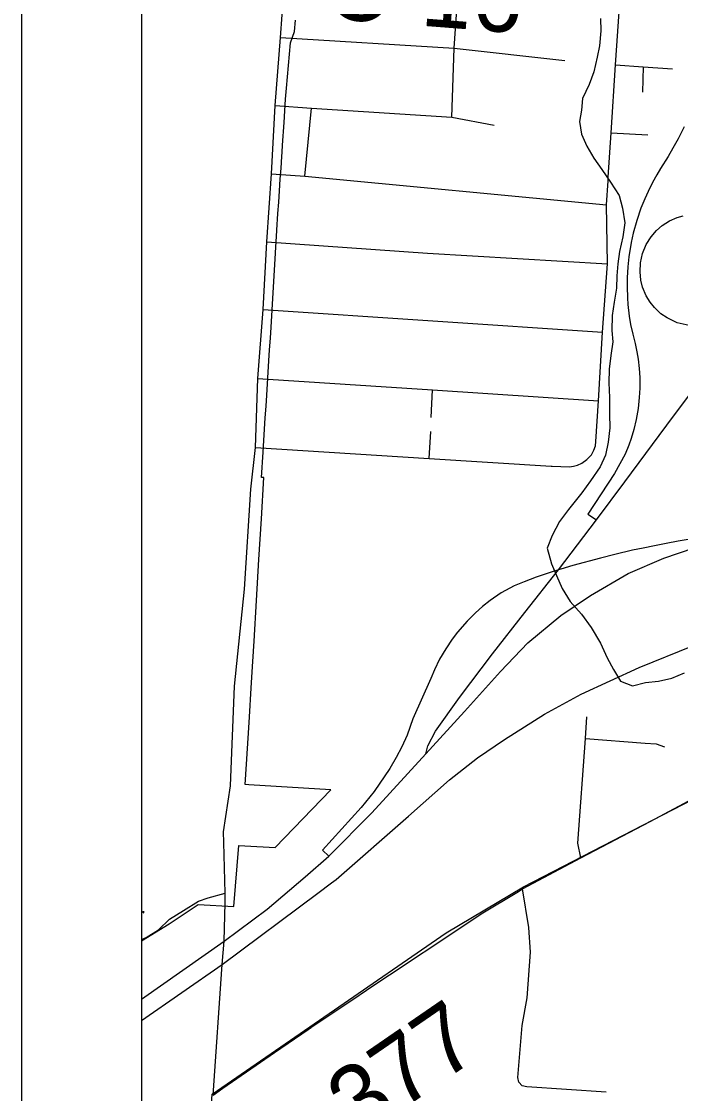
# Model space of a CAD drawing. Extents: x 208586767.6 to 208586821.4, y -134301046.9 to -134301022.9.
# Drawn here: x 208586777.928 to 208586778.476, y -134301030.451 to -134301029.559 of the extents above; entities that cross this region are included whole.
import ezdxf

# ---------------------------------------------------------------- set-up
doc = ezdxf.new("R2010")
doc.units = 0
for name, color, linetype in [('GM_X_City_Street', 7, 'Continuous'), ('GM_X_Corporation', 7, 'Continuous'), ('GM_X_County_Road', 7, 'Continuous'), ('GM_X_County_Road_Text', 7, 'Continuous'), ('GM_X_Interchange_Ramps', 7, 'Continuous'), ('GM_X_Interstate_Route', 7, 'Continuous'), ('GM_X_Minor_River', 7, 'Continuous'), ('GM_X_Rail_Line', 7, 'Continuous'), ('GM_X_Township_Road', 7, 'Continuous'), ('GM_X_US_Route', 7, 'Continuous'), ('SH_Data', 7, 'Continuous')]:
    doc.layers.add(name, color=color, linetype=linetype)

msp = doc.modelspace()

# ---------------------------------------------------------------- linework, layer by layer
at = {"layer": 'GM_X_City_Street'}
msp.add_lwpolyline([(208586778.41474, -134301030.44948), (208586778.34869, -134301030.44514), (208586778.34476, -134301030.44426), (208586778.34194, -134301030.4414), (208586778.34112, -134301030.43746), (208586778.34483, -134301030.39406), (208586778.34883, -134301030.37122), (208586778.35154, -134301030.33312), (208586778.35037, -134301030.31257), (208586778.34509, -134301030.28063)], dxfattribs=at)
at = {"layer": 'GM_X_Corporation'}
for points in [[(208586778.02826, -134301025.18459), (208586778.02826, -134301030.32371), (208586778.05119, -134301030.30976), (208586778.07514, -134301030.29348), (208586778.10481, -134301030.29512), (208586778.10901, -134301030.2444), (208586778.11421, -134301030.24486), (208586778.13931, -134301030.2462), (208586778.18558, -134301030.19823), (208586778.1173, -134301030.19406), (208586778.11446, -134301030.19389), (208586778.11549, -134301030.17691), (208586778.1176, -134301030.14213), (208586778.11963, -134301030.10887), (208586778.12067, -134301030.0916), (208586778.1217, -134301030.07469), (208586778.12376, -134301030.0408), (208586778.12583, -134301030.0068), (208586778.12789, -134301029.97281), (208586778.12997, -134301029.93865), (208586778.12789, -134301029.93851), (208586778.1293, -134301029.91742), (208586778.12984, -134301029.90774), (208586778.13044, -134301029.8985), (208586778.13106, -134301029.88898), (208586778.13169, -134301029.87934), (208586778.13229, -134301029.87005), (208586778.1329, -134301029.86056), (208586778.13355, -134301029.85095), (208586778.13413, -134301029.84166), (208586778.13469, -134301029.83249), (208586778.13529, -134301029.82283), (208586778.13586, -134301029.81355), (208586778.13645, -134301029.80405), (208586778.13703, -134301029.79437), (208586778.13758, -134301029.78506), (208586778.13813, -134301029.77572), (208586778.1387, -134301029.76613), (208586778.13926, -134301029.75668), (208586778.13983, -134301029.74717), (208586778.14038, -134301029.73798), (208586778.14102, -134301029.72835), (208586778.14132, -134301029.72374), (208586778.14163, -134301029.71904), (208586778.14225, -134301029.70961), (208586778.14288, -134301029.7001), (208586778.1435, -134301029.69061), (208586778.14424, -134301029.68128), (208586778.14486, -134301029.67177), (208586778.1451, -134301029.66803), (208586778.14546, -134301029.66236), (208586778.14668, -134301029.64333), (208586778.1473, -134301029.63369), (208586778.14802, -134301029.62415), (208586778.14882, -134301029.61501), (208586778.14965, -134301029.60558), (208586778.15049, -134301029.5961), (208586778.15132, -134301029.58672), (208586778.15216, -134301029.57717), (208586778.1554, -134301029.56777), (208586778.15619, -134301029.55835)], [(208586778.02826, -134301026.87222), (208586778.02826, -134301030.84072), (208586780.45606, -134301030.84072), (208586780.46226, -134301030.73232), (208586780.4715, -134301030.56429), (208586780.4725, -134301030.5433), (208586780.47482, -134301030.49456), (208586780.47836, -134301030.43953), (208586780.48165, -134301030.41091), (208586780.49647, -134301030.208), (208586780.51007, -134301029.93716), (208586780.52674, -134301029.60513), (208586780.54433, -134301029.31871), (208586780.54744, -134301029.28003), (208586780.55021, -134301029.2296), (208586780.55566, -134301029.13188), (208586780.5628, -134301029.05207), (208586780.56784, -134301028.98117), (208586780.57226, -134301028.915), (208586780.57856, -134301028.81386), (208586780.60576, -134301028.40742)]]:
    msp.add_lwpolyline(points, dxfattribs=at)
at = {"layer": 'GM_X_County_Road'}
msp.add_line((208586778.08778, -134301030.45204), (208586778.09587, -134301030.4464), dxfattribs=at)
for points in [[(208586778.09662, -134301030.24215), (208586778.09638, -134301030.23312), (208586778.1022, -134301030.19496), (208586778.10543, -134301030.11216), (208586778.11384, -134301030.03128), (208586778.11894, -134301029.94838), (208586778.1229, -134301029.91373), (208586778.12488, -134301029.85633), (208586778.12933, -134301029.79892), (208586778.1323, -134301029.7425), (208586778.13626, -134301029.68608), (208586778.13923, -134301029.62917), (208586778.14368, -134301029.57275), (208586778.14783, -134301029.51583), (208586778.15165, -134301029.45691), (208586778.15187, -134301029.4532), (208586778.15344, -134301029.42722)], [(208586778.34173, -134301030.28266), (208586778.34509, -134301030.28063), (208586778.39368, -134301030.25482), (208586778.45133, -134301030.22449), (208586778.5031, -134301030.19684), (208586778.54251, -134301030.17641)], [(208586778.09758, -134301030.29227), (208586778.09776, -134301030.28429), (208586778.09662, -134301030.24215)], [(208586778.23453, -134301030.352), (208586778.29136, -134301030.31426), (208586778.31066, -134301030.30141), (208586778.34173, -134301030.28266)], [(208586778.08778, -134301030.45204), (208586778.09522, -134301030.34335), (208586778.09683, -134301030.32418), (208586778.09758, -134301030.29227)], [(208586778.20999, -134301030.3684), (208586778.22053, -134301030.3613), (208586778.23453, -134301030.352)], [(208586778.18561, -134301030.38483), (208586778.18643, -134301030.38427), (208586778.20918, -134301030.36894), (208586778.20999, -134301030.3684)], [(208586778.16911, -134301030.39594), (208586778.1699, -134301030.39541), (208586778.17817, -134301030.38984), (208586778.18561, -134301030.38483)], [(208586778.09587, -134301030.4464), (208586778.13874, -134301030.41652), (208586778.16675, -134301030.39753), (208586778.16911, -134301030.39594)]]:
    msp.add_lwpolyline(points, dxfattribs=at)
at = {"layer": 'GM_X_Interchange_Ramps'}
for points in [[(208586778.47941, -134301029.64708), (208586778.47442, -134301029.65697), (208586778.47014, -134301029.66481), (208586778.46614, -134301029.67169), (208586778.45983, -134301029.68164), (208586778.45672, -134301029.68682), (208586778.45307, -134301029.69344), (208586778.44943, -134301029.70075), (208586778.44664, -134301029.70702), (208586778.44357, -134301029.71471), (208586778.44008, -134301029.72501), (208586778.4372, -134301029.73554), (208586778.43553, -134301029.74309), (208586778.43354, -134301029.75522), (208586778.43268, -134301029.76332), (208586778.43213, -134301029.77269), (208586778.43202, -134301029.78012), (208586778.43231, -134301029.78923), (208586778.43271, -134301029.79474), (208586778.43379, -134301029.80435), (208586778.43494, -134301029.81146), (208586778.43671, -134301029.8195), (208586778.43874, -134301029.82717), (208586778.44019, -134301029.83408), (208586778.44118, -134301029.84009), (208586778.44208, -134301029.84784), (208586778.44254, -134301029.85531), (208586778.44259, -134301029.86435), (208586778.44219, -134301029.87212), (208586778.44119, -134301029.88124), (208586778.43961, -134301029.89029), (208586778.43761, -134301029.89871), (208586778.43538, -134301029.90615), (208586778.4335, -134301029.91155), (208586778.43038, -134301029.91928), (208586778.42158, -134301029.93532), (208586778.3995, -134301029.96915), (208586778.40669, -134301029.97371)], [(208586778.48359, -134301029.81225), (208586778.47364, -134301029.80992), (208586778.46524, -134301029.80595), (208586778.4602, -134301029.80243), (208586778.4548, -134301029.79736), (208586778.45115, -134301029.79281), (208586778.44794, -134301029.78748), (208586778.44496, -134301029.7803), (208586778.44352, -134301029.77459), (208586778.44277, -134301029.7676), (208586778.44314, -134301029.76009), (208586778.44483, -134301029.75241), (208586778.4479, -134301029.7449), (208586778.452, -134301029.73835), (208586778.45643, -134301029.73324), (208586778.46121, -134301029.72909), (208586778.46716, -134301029.72527), (208586778.47367, -134301029.7224), (208586778.47857, -134301029.72095)], [(208586778.48269, -134301029.99021), (208586778.47442, -134301029.99159), (208586778.46439, -134301029.99339), (208586778.45468, -134301029.99526), (208586778.44528, -134301029.9972), (208586778.43649, -134301029.99912), (208586778.42195, -134301030.00255), (208586778.40978, -134301030.00564), (208586778.38676, -134301030.01174), (208586778.37691, -134301030.01466), (208586778.37491, -134301030.0153), (208586778.36713, -134301030.0178), (208586778.35628, -134301030.02157), (208586778.34651, -134301030.02523), (208586778.33816, -134301030.02856), (208586778.32735, -134301030.03447), (208586778.31813, -134301030.04082), (208586778.31174, -134301030.04587), (208586778.3058, -134301030.05111), (208586778.29899, -134301030.05788), (208586778.29095, -134301030.06715), (208586778.28661, -134301030.07286), (208586778.2812, -134301030.08091), (208586778.27609, -134301030.08974), (208586778.27175, -134301030.09856), (208586778.26874, -134301030.10572), (208586778.25383, -134301030.13915), (208586778.24905, -134301030.15276), (208586778.24459, -134301030.16254), (208586778.23991, -134301030.17147), (208586778.2346, -134301030.18061), (208586778.22164, -134301030.19974), (208586778.2108, -134301030.21292), (208586778.1786, -134301030.24848), (208586778.18381, -134301030.25349)]]:
    msp.add_lwpolyline(points, dxfattribs=at)
at = {"layer": 'GM_X_Interstate_Route'}
for points in [[(208586778.18381, -134301030.25349), (208586778.21969, -134301030.21735), (208586778.26466, -134301030.16841), (208586778.29684, -134301030.13318), (208586778.32678, -134301030.09973), (208586778.34944, -134301030.07599), (208586778.37695, -134301030.05333), (208586778.4015, -134301030.03661), (208586778.4328, -134301030.01826), (208586778.46247, -134301030.00558), (208586778.48783, -134301029.99695)], [(208586778.1862, -134301030.27557), (208586778.19002, -134301030.27274), (208586778.25029, -134301030.2201), (208586778.28433, -134301030.19004), (208586778.30751, -134301030.17172), (208586778.33004, -134301030.15641), (208586778.36346, -134301030.13535), (208586778.39373, -134301030.11877), (208586778.44216, -134301030.0964), (208586778.48716, -134301030.07838)], [(208586778.02826, -134301030.37215), (208586778.09683, -134301030.32418), (208586778.13259, -134301030.29755), (208586778.16438, -134301030.27049), (208586778.18381, -134301030.25349)], [(208586778.02826, -134301030.39013), (208586778.09522, -134301030.34335), (208586778.17475, -134301030.28406), (208586778.1862, -134301030.27557)]]:
    msp.add_lwpolyline(points, dxfattribs=at)
at = {"layer": 'GM_X_Minor_River'}
for points in [[(208586778.41, -134301029.5569), (208586778.41028, -134301029.56715), (208586778.40904, -134301029.57967), (208586778.40705, -134301029.58915), (208586778.40429, -134301029.60127), (208586778.40041, -134301029.61187), (208586778.39499, -134301029.62359), (208586778.39415, -134301029.63307), (208586778.39255, -134301029.64255), (208586778.39397, -134301029.6532), (208586778.39843, -134301029.66311), (208586778.4044, -134301029.67304)], [(208586778.4044, -134301029.67304), (208586778.41114, -134301029.68259), (208586778.41824, -134301029.69291), (208586778.42535, -134301029.70399), (208586778.42828, -134301029.71465), (208586778.43007, -134301029.72682), (208586778.42844, -134301029.73857), (208586778.42568, -134301029.7507), (208586778.42445, -134301029.76094), (208586778.42361, -134301029.7708), (208586778.42313, -134301029.78105), (208586778.42113, -134301029.7928), (208586778.41952, -134301029.8038), (208586778.41941, -134301029.81633), (208586778.42008, -134301029.82583), (208586778.41846, -134301029.83721), (208586778.41722, -134301029.84859), (208586778.41674, -134301029.85997), (208586778.41739, -134301029.87213), (208586778.41726, -134301029.8858), (208586778.41754, -134301029.89719), (208586778.41629, -134301029.90933), (208586778.41392, -134301029.91994), (208586778.40966, -134301029.92977), (208586778.4016, -134301029.94147), (208586778.39431, -134301029.95128), (208586778.38319, -134301029.96522), (208586778.3759, -134301029.97502), (208586778.36973, -134301029.98674), (208586778.36547, -134301029.99733), (208586778.36914, -134301030.01028), (208586778.37322, -134301030.02018), (208586778.37805, -134301030.03086), (208586778.38478, -134301030.04156), (208586778.39416, -134301030.05228), (208586778.40201, -134301030.06336), (208586778.40986, -134301030.07635), (208586778.41543, -134301030.08855), (208586778.42065, -134301030.09809), (208586778.42662, -134301030.10802), (208586778.43644, -134301030.11191), (208586778.44746, -134301030.10897), (208586778.45808, -134301030.10793), (208586778.4691, -134301030.10538), (208586778.47975, -134301030.10092)], [(208586778.02826, -134301030.29874), (208586778.02996, -134301030.30062), (208586778.02998, -134301030.2991)]]:
    msp.add_lwpolyline(points, dxfattribs=at)
at = {"layer": 'GM_X_Rail_Line'}
msp.add_lwpolyline([(208586778.06, -134301030.84072), (208586778.08678, -134301030.45133), (208586778.28158, -134301030.31705), (208586778.34586, -134301030.27885), (208586778.83474, -134301030.02645), (208586778.98539, -134301029.93873), (208586779.19632, -134301029.79893), (208586779.44742, -134301029.66561), (208586779.67843, -134301029.61252), (208586779.77157, -134301029.57963)], dxfattribs=at)
at = {"layer": 'GM_X_Township_Road'}
for p, q in [((208586778.44543, -134301029.59715), (208586778.44477, -134301029.61826)), ((208586778.16398, -134301029.68806), (208586778.16942, -134301029.63164)), ((208586778.41881, -134301029.6521), (208586778.44918, -134301029.65368)), ((208586778.12933, -134301029.79892), (208586778.41148, -134301029.81761)), ((208586778.26894, -134301029.88873), (208586778.27014, -134301029.86563)), ((208586778.26732, -134301029.92275), (208586778.26884, -134301029.90041))]:
    msp.add_line(p, q, dxfattribs=at)
for points in [[(208586778.28622, -134301029.63906), (208586778.28819, -134301029.58166), (208586778.29216, -134301029.52524), (208586778.29612, -134301029.46783)], [(208586778.41621, -134301029.69194), (208586778.4164, -134301029.68897), (208586778.41881, -134301029.6521), (208586778.4225, -134301029.59552), (208586778.42617, -134301029.53928), (208586778.42785, -134301029.50707)], [(208586778.14368, -134301029.57275), (208586778.28819, -134301029.58166), (208586778.38016, -134301029.5918)], [(208586778.4225, -134301029.59552), (208586778.44543, -134301029.59715), (208586778.46976, -134301029.59887)], [(208586778.13923, -134301029.62917), (208586778.16942, -134301029.63164), (208586778.28622, -134301029.63906), (208586778.32159, -134301029.64564)], [(208586778.13626, -134301029.68608), (208586778.16398, -134301029.68806), (208586778.41492, -134301029.71175)], [(208586778.39449, -134301029.92676), (208586778.39861, -134301029.9237), (208586778.40232, -134301029.91984), (208586778.4043, -134301029.91593), (208586778.40563, -134301029.91222), (208586778.40611, -134301029.90856), (208586778.4082, -134301029.87487), (208586778.41148, -134301029.81761), (208586778.41566, -134301029.76096), (208586778.41492, -134301029.71175), (208586778.41621, -134301029.69194)], [(208586778.1323, -134301029.7425), (208586778.26596, -134301029.75201), (208586778.41566, -134301029.76096)], [(208586778.12488, -134301029.85633), (208586778.27014, -134301029.86563), (208586778.4082, -134301029.87487)], [(208586778.1229, -134301029.91373), (208586778.26732, -134301029.92275), (208586778.36884, -134301029.92914), (208586778.36969, -134301029.92917)], [(208586778.36969, -134301029.92917), (208586778.38407, -134301029.92964), (208586778.38758, -134301029.92919), (208586778.39069, -134301029.92835), (208586778.39449, -134301029.92676)], [(208586778.39368, -134301030.25482), (208586778.39105, -134301030.24255), (208586778.39736, -134301030.15563), (208586778.39866, -134301030.13758)], [(208586778.39736, -134301030.15563), (208586778.44692, -134301030.15937), (208586778.45616, -134301030.16008), (208586778.46317, -134301030.16243)], [(208586778.02826, -134301030.32256), (208586778.03205, -134301030.32096), (208586778.04221, -134301030.3146), (208586778.05152, -134301030.30571), (208586778.06295, -134301030.29851), (208586778.07566, -134301030.29089), (208586778.0837, -134301030.28792), (208586778.09776, -134301030.28429)]]:
    msp.add_lwpolyline(points, dxfattribs=at)
at = {"layer": 'GM_X_US_Route'}
for points in [[(208586778.26466, -134301030.16841), (208586778.26632, -134301030.16167), (208586778.27258, -134301030.14951), (208586778.29254, -134301030.12156), (208586778.32013, -134301030.08523), (208586778.34704, -134301030.05068), (208586778.37491, -134301030.0153), (208586778.40669, -134301029.97371), (208586778.43015, -134301029.94212), (208586778.47073, -134301029.88751), (208586778.51196, -134301029.83268)], [(208586778.1862, -134301030.27557), (208586778.19002, -134301030.27274), (208586778.25029, -134301030.2201), (208586778.28433, -134301030.19004), (208586778.30751, -134301030.17172), (208586778.33004, -134301030.15641), (208586778.36346, -134301030.13535), (208586778.39373, -134301030.11877), (208586778.44216, -134301030.0964), (208586778.48716, -134301030.07838)], [(208586778.02826, -134301030.39013), (208586778.09522, -134301030.34335), (208586778.17475, -134301030.28406), (208586778.1862, -134301030.27557)]]:
    msp.add_lwpolyline(points, dxfattribs=at)
at = {"layer": 'SH_Data'}
for p, q in [((208586777.92826, -134301023.94072), (208586777.92826, -134301030.94072)), ((208586778.02826, -134301024.04072), (208586778.02826, -134301030.84072))]:
    msp.add_line(p, q, dxfattribs=at)

# ---------------------------------------------------------------- texts
at = {"layer": 'GM_X_County_Road_Text'}
for s, rotation, p in [('C-16', 355.55756, (208586778.17948, -134301029.55662)), ('C-377', 34.50889, (208586778.1428, -134301030.53459))]:
    msp.add_text(s, height=0.056818, rotation=rotation, dxfattribs=at).set_placement(p)

doc.saveas('drawing.dxf')
